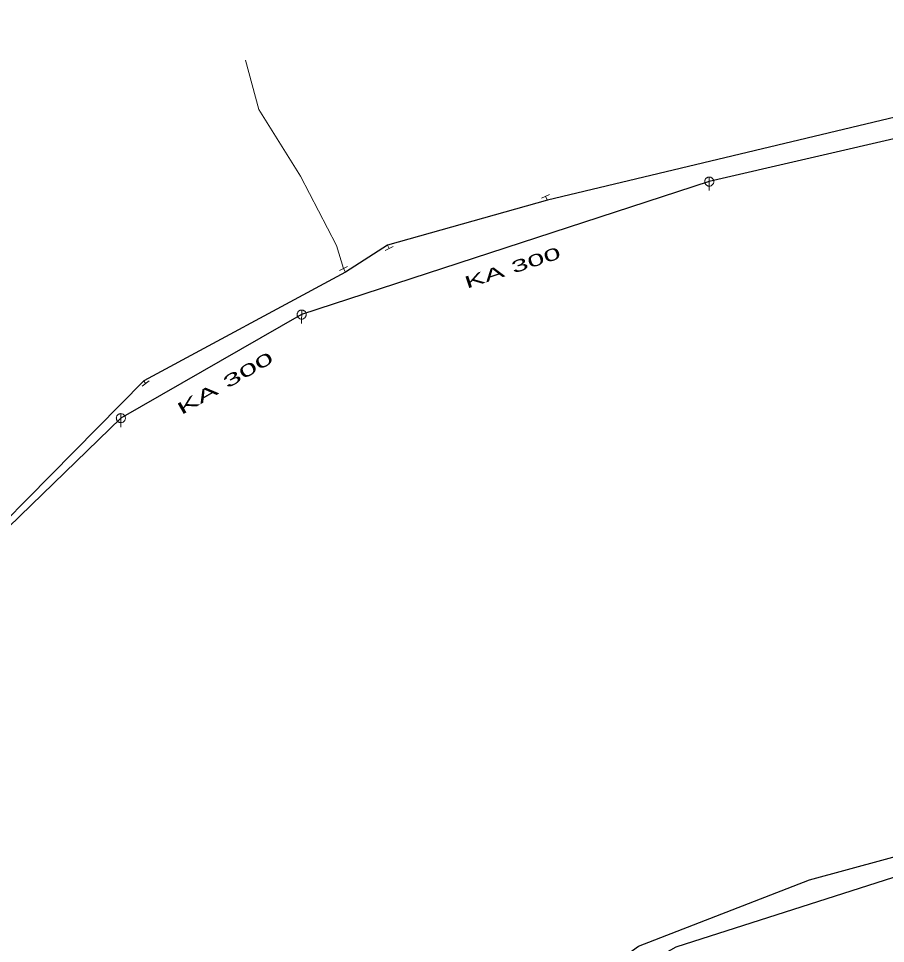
# Model space of a CAD drawing. Extents: x -687515 to -686506, y -974029 to -973461.
# Drawn here: x -687063.3 to -687015, y -973804.9 to -973753.4 of the extents above; entities that cross this region are included whole.
import ezdxf
from ezdxf.enums import TextEntityAlignment as Align

# ---------------------------------------------------------------- set-up
doc = ezdxf.new("R2010")
doc.units = 0
doc.header["$LTSCALE"] = 0.27
for name, color, linetype, lineweight in [('1', 7, 'Continuous', 13), ('13', 7, 'Continuous', 13), ('14', 7, 'Continuous', 25), ('17', 7, 'Continuous', 25), ('22', 7, 'Continuous', 13), ('34', 7, 'Continuous', 13)]:
    doc.layers.add(name, color=color, linetype=linetype, lineweight=lineweight)

msp = doc.modelspace()

# ---------------------------------------------------------------- linework, layer by layer
at = {"layer": '13'}
msp.add_lwpolyline([(-687045.189, -973767.309), (-687045.57, -973766.039), (-687047.57, -973762.18), (-687049.899, -973758.46), (-687050.64, -973755.73)], dxfattribs=at)
at = {"layer": '14'}
for p, q in [((-686991.899, -973754.84), (-687024.84, -973762.48)), ((-687024.84, -973762.48), (-687047.51, -973769.879)), ((-687047.51, -973769.879), (-687057.566, -973775.642)), ((-687057.566, -973775.642), (-687079.592, -973797.014))]:
    msp.add_line(p, q, dxfattribs=at)
at = {"layer": '14', "lineweight": 13}
for p, q in [((-687033.846, -973763.506), (-687033.949, -973763.299)), ((-687042.734, -973766.009), (-687042.639, -973766.199)), ((-687045.081, -973767.522), (-687045.189, -973767.309)), ((-687056.296, -973773.572), (-687056.19, -973773.709))]:
    msp.add_line(p, q, dxfattribs=at)
at = {"layer": '14'}
msp.add_lwpolyline([(-687012.736, -973800.616), (-687026.707, -973805.08), (-687035.055, -973809.776), (-687046.647, -973818.78)], dxfattribs=at)
at = {"layer": '17'}
for points in [[(-686989.707, -973753.404), (-687001.294, -973755.738), (-687033.846, -973763.506), (-687042.734, -973766.009), (-687045.081, -973767.522), (-687056.296, -973773.572), (-687070.532, -973788), (-687086.733, -973803.447)], [(-687075.086, -973853.519), (-687063.695, -973837.3), (-687051.693, -973822.548), (-687047.027, -973818.188), (-687028.776, -973805.013), (-687019.272, -973801.323), (-687004.054, -973797.199), (-686987.892, -973793.361), (-686982.074, -973791.647), (-686976.761, -973790.276)]]:
    msp.add_lwpolyline(points, dxfattribs=at)
at = {"layer": '22'}
for p, q in [((-687024.839, -973762.228), (-687024.84, -973762.972)), ((-687047.509, -973769.627), (-687047.51, -973770.37)), ((-687057.565, -973775.39), (-687057.566, -973776.134))]:
    msp.add_line(p, q, dxfattribs=at)
for points in [[(-687024.588, -973762.48), (-687024.589, -973762.454), (-687024.593, -973762.428), (-687024.599, -973762.402), (-687024.609, -973762.378), (-687024.621, -973762.354), (-687024.635, -973762.332), (-687024.652, -973762.311), (-687024.67, -973762.293), (-687024.691, -973762.276), (-687024.713, -973762.262), (-687024.737, -973762.25), (-687024.761, -973762.24), (-687024.787, -973762.234), (-687024.813, -973762.23), (-687024.839, -973762.228), (-687024.865, -973762.229), (-687024.891, -973762.233), (-687024.917, -973762.239), (-687024.942, -973762.249), (-687024.965, -973762.261), (-687024.987, -973762.275), (-687025.008, -973762.292), (-687025.026, -973762.31), (-687025.043, -973762.331), (-687025.057, -973762.353), (-687025.069, -973762.377), (-687025.079, -973762.401), (-687025.086, -973762.427), (-687025.09, -973762.453), (-687025.092, -973762.479), (-687025.091, -973762.505), (-687025.087, -973762.531), (-687025.08, -973762.557), (-687025.07, -973762.582), (-687025.058, -973762.605), (-687025.044, -973762.627), (-687025.027, -973762.648), (-687025.009, -973762.666), (-687024.988, -973762.683), (-687024.966, -973762.697), (-687024.943, -973762.709), (-687024.918, -973762.719), (-687024.892, -973762.726), (-687024.866, -973762.73), (-687024.84, -973762.732), (-687024.814, -973762.731), (-687024.788, -973762.727), (-687024.762, -973762.72), (-687024.738, -973762.71), (-687024.714, -973762.698), (-687024.692, -973762.684), (-687024.671, -973762.667), (-687024.653, -973762.649), (-687024.636, -973762.628), (-687024.622, -973762.606), (-687024.61, -973762.583), (-687024.6, -973762.558), (-687024.594, -973762.532), (-687024.59, -973762.506)], [(-687047.258, -973769.879), (-687047.259, -973769.853), (-687047.263, -973769.827), (-687047.269, -973769.801), (-687047.279, -973769.777), (-687047.291, -973769.753), (-687047.305, -973769.731), (-687047.322, -973769.71), (-687047.34, -973769.692), (-687047.361, -973769.675), (-687047.383, -973769.661), (-687047.407, -973769.649), (-687047.431, -973769.639), (-687047.457, -973769.633), (-687047.483, -973769.629), (-687047.509, -973769.627), (-687047.535, -973769.628), (-687047.561, -973769.632), (-687047.587, -973769.638), (-687047.612, -973769.648), (-687047.635, -973769.66), (-687047.657, -973769.674), (-687047.678, -973769.691), (-687047.696, -973769.709), (-687047.713, -973769.73), (-687047.727, -973769.752), (-687047.739, -973769.776), (-687047.749, -973769.8), (-687047.756, -973769.826), (-687047.76, -973769.852), (-687047.762, -973769.878), (-687047.761, -973769.904), (-687047.757, -973769.93), (-687047.75, -973769.956), (-687047.74, -973769.981), (-687047.728, -973770.004), (-687047.714, -973770.026), (-687047.697, -973770.047), (-687047.679, -973770.065), (-687047.658, -973770.082), (-687047.636, -973770.096), (-687047.613, -973770.108), (-687047.588, -973770.118), (-687047.562, -973770.125), (-687047.536, -973770.129), (-687047.51, -973770.13), (-687047.484, -973770.13), (-687047.458, -973770.126), (-687047.432, -973770.119), (-687047.408, -973770.109), (-687047.384, -973770.097), (-687047.362, -973770.083), (-687047.341, -973770.066), (-687047.323, -973770.048), (-687047.306, -973770.027), (-687047.292, -973770.005), (-687047.28, -973769.982), (-687047.27, -973769.957), (-687047.264, -973769.931), (-687047.26, -973769.905)], [(-687057.314, -973775.642), (-687057.315, -973775.616), (-687057.319, -973775.59), (-687057.325, -973775.564), (-687057.335, -973775.54), (-687057.347, -973775.516), (-687057.361, -973775.494), (-687057.378, -973775.473), (-687057.396, -973775.455), (-687057.417, -973775.438), (-687057.439, -973775.424), (-687057.463, -973775.412), (-687057.487, -973775.402), (-687057.513, -973775.396), (-687057.539, -973775.392), (-687057.565, -973775.39), (-687057.591, -973775.391), (-687057.617, -973775.395), (-687057.643, -973775.401), (-687057.668, -973775.411), (-687057.691, -973775.423), (-687057.713, -973775.437), (-687057.734, -973775.454), (-687057.752, -973775.472), (-687057.769, -973775.493), (-687057.783, -973775.515), (-687057.795, -973775.539), (-687057.805, -973775.563), (-687057.812, -973775.589), (-687057.816, -973775.615), (-687057.818, -973775.641), (-687057.817, -973775.667), (-687057.813, -973775.693), (-687057.806, -973775.719), (-687057.796, -973775.744), (-687057.784, -973775.767), (-687057.77, -973775.789), (-687057.753, -973775.81), (-687057.735, -973775.828), (-687057.714, -973775.845), (-687057.692, -973775.859), (-687057.669, -973775.871), (-687057.644, -973775.881), (-687057.618, -973775.888), (-687057.592, -973775.892), (-687057.566, -973775.894), (-687057.54, -973775.893), (-687057.514, -973775.889), (-687057.488, -973775.882), (-687057.464, -973775.872), (-687057.44, -973775.86), (-687057.418, -973775.846), (-687057.397, -973775.829), (-687057.379, -973775.811), (-687057.362, -973775.79), (-687057.348, -973775.768), (-687057.336, -973775.745), (-687057.326, -973775.72), (-687057.32, -973775.694), (-687057.316, -973775.668)]]:
    msp.add_lwpolyline(points, close=True, dxfattribs=at)
at = {"layer": '34'}
for p, q in [((-687034.171, -973763.409), (-687033.726, -973763.188)), ((-687042.861, -973766.308), (-687042.416, -973766.089)), ((-687045.41, -973767.421), (-687044.967, -973767.196)), ((-687056.385, -973773.86), (-687055.994, -973773.557))]:
    msp.add_line(p, q, dxfattribs=at)

# ---------------------------------------------------------------- texts
at = {"layer": '1'}
for rotation, width, p in [(18, 1.9, (-687035.681, -973767.583)), (30, 2.05, (-687051.603, -973773.983))]:
    msp.add_text('KA 300', height=0.6667, rotation=rotation, dxfattribs=dict(at, width=width)).set_placement(p, align=Align.CENTER)

doc.saveas('drawing.dxf')
